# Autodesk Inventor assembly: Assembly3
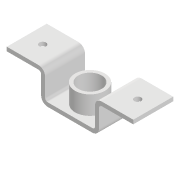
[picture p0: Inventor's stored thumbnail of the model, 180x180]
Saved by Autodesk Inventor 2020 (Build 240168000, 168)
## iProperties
Created: 2019-06
Part Number: Assembly3
Document SubType Name: Weldment
Designer: LENOVO-CADCIM
Weld Material: Welded Aluminum-6061
Author: LENOVO-CADCIM
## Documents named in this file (3)
- D:\Autodesk Inventor_2020\Resources\Resources\Inventor_2020_tut\Inventor_2020_tut\c16_Inv_2020_tut\c16_Inv_tut_2020\c16_tut02\Assembly3.iam
- D:\Autodesk Inventor_2020\Resources\Resources\Inventor_2020_tut\Inventor_2020_tut\c16_Inv_2020_tut\c16_Inv_tut_2020\c16_tut02\Bracket.ipt
- D:\Autodesk Inventor_2020\Resources\Resources\Inventor_2020_tut\Inventor_2020_tut\c16_Inv_2020_tut\c16_Inv_tut_2020\c16_tut02\Cylinder.ipt
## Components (2 placed, 2 different names)
1. Bracket:1 — Insert:1
2. Cylinder:1 — Insert:1
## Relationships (1: Insert 1)
- Insert:1: Bracket:1 ↔ Cylinder:1
